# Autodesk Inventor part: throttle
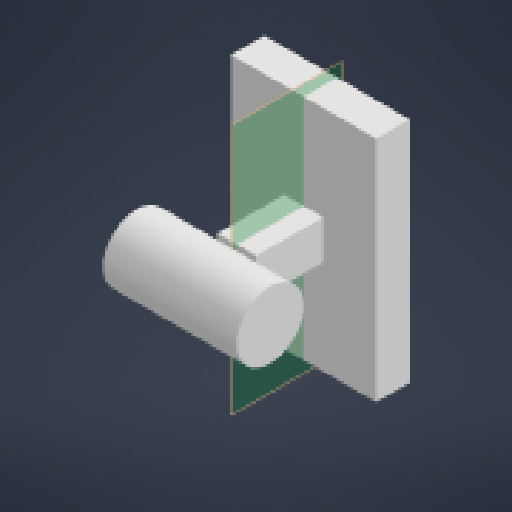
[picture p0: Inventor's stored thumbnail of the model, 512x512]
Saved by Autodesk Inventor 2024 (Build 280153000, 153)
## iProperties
Created: 2023-09
Part Number: throttle
Material: Generic
Document SubType Name: Modeling
Designer: mammothbane
Density: 1 g/cm^3
Appearance: Default
Author: mammothbane
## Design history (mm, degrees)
sketch "Sketch1"
  geometry: L1 (-65.182, 102.449)-(65.182, 102.449); L2 (65.182, 102.449)-(65.182, -102.449); L3 (65.182, -102.449)-(-65.182, -102.449); L4 (-65.182, -102.449)-(-65.182, 102.449); L5 (-65.182, 102.449)-(65.182, -102.449); L6 (65.182, 102.449)-(-65.182, -102.449); 1 further point
  constraints: 12 end point, 2 midpoint, 2 parallel, 1 horizontal, 1 perpendicular
extrude "Extrusion1" new body sketch "Sketch1" distance "d0" = 30; taper "d1" = 0 deg
sketch "Sketch2"
  geometry: L1 (-17.5, 17.5)-(17.5, 17.5); L2 (17.5, 17.5)-(17.5, -17.5); L3 (17.5, -17.5)-(-17.5, -17.5); L4 (-17.5, -17.5)-(-17.5, 17.5); L5 (-17.5, 17.5)-(17.5, -17.5); L6 (17.5, 17.5)-(-17.5, -17.5); 1 further point
  constraints: 12 end point, 2 midpoint, 2 parallel, 1 horizontal, 1 perpendicular
  dimensions: "d2" = 35 distance of L1.end L2.end; "d3" = 35 distance of L2.end L3.end
extrude "Extrusion2" join sketch "Sketch2" distance "d4" = 60; taper "d5" = 0 deg
workplane "Work Plane1"
sketch "Sketch3"
  geometry: L1 (60, 35)-(60, 0) reference; C1 r 30 at (90, 17.5); 1 further point
  constraints: 1 centre point, 1 tangent
  dimensions: "d6" = 60 diameter of C1
extrude "Extrusion3" join sketch "Sketch3" stored distance "d7" = 120; taper "d8" = 0 deg
body "Solid1"
